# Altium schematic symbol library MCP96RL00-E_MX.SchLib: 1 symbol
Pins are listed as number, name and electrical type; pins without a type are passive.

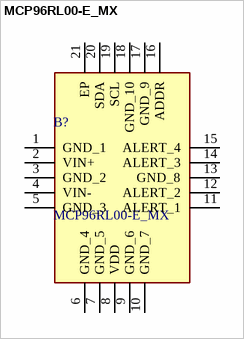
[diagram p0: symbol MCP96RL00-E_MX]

## MCP96RL00-E_MX
designator B?
Board Mount Temperature Sensors +/- 8.0C Thermocouple to I2C converter in 5mmx5mm QFN. This device supports K, J, T, N, S, E, B, and R type thermocouples.; Manufacturer_Name: Microchip; Manufacturer_Part_Number: MCP96RL00-E/MX; Geometry.Height: 1mm
footprint QFN65P500X500X100-21N-D
pins: 1 GND_1, 2 VIN+, 3 GND_2, 4 VIN-, 5 GND_3, 6 GND_4, 7 GND_5, 8 VDD, 9 GND_6, 10 GND_7, 11 ALERT_1, 12 ALERT_2, 13 GND_8, 14 ALERT_3, 15 ALERT_4, 16 ADDR, 17 GND_9, 18 GND_10, 19 SCL, 20 SDA, 21 EP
